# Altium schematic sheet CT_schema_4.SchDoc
size 187 x 159 mm
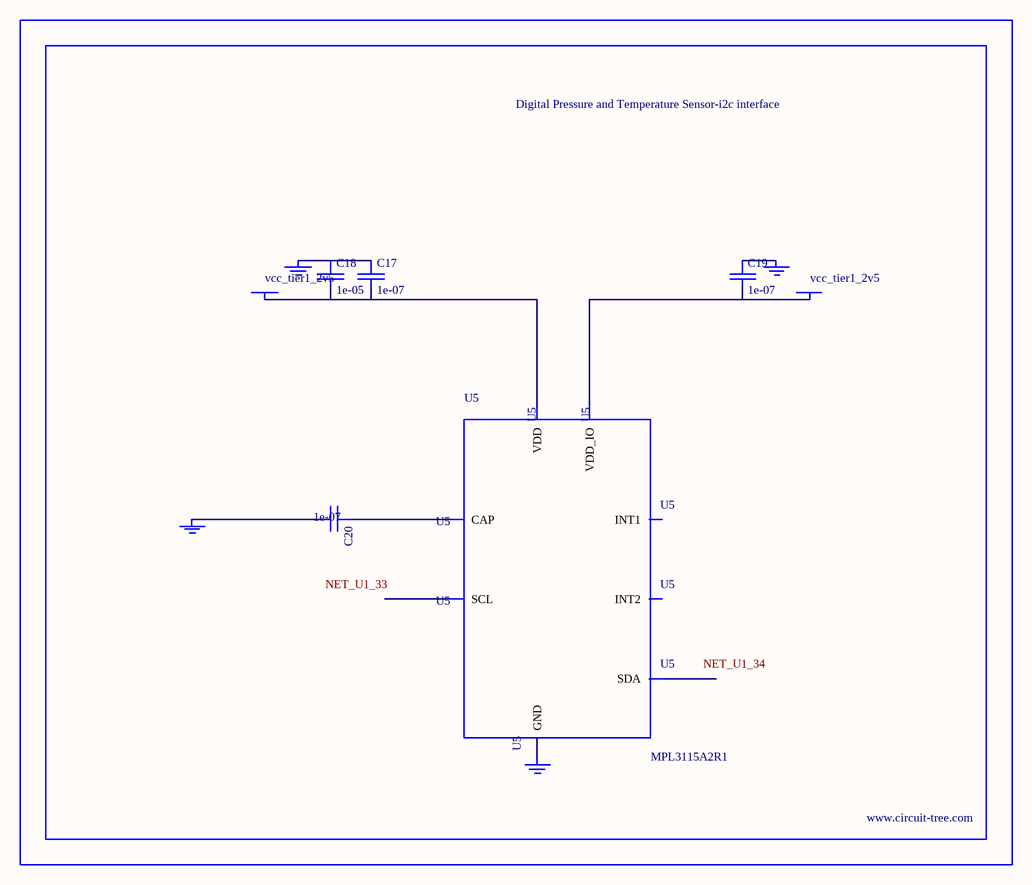
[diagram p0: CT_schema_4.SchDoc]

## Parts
BORDER3  (no value)
C17  1e-07  [C0402]
C18  1e-05  [C0805]
C19  1e-07  [C0402]
C20  1e-07  [C0402]
GND_INSTANCE_3_0  (no value)
GND_INSTANCE_3_1  (no value)
GND_INSTANCE_3_2  (no value)
GND_INSTANCE_3_3  (no value)
POWER_INSTANCE_3_0  vcc_tier1_2v5
POWER_INSTANCE_3_1  vcc_tier1_2v5
U5  MPL3115A2R1  [LGA-8]

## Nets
NetC17_1: C17.1 C18.1 GND_INSTANCE_3_0.0(GND)
NetC17_2: C17.2 C18.2 POWER_INSTANCE_3_0.0(PWR) U5.1(VDD)
NetC19_1: C19.1 GND_INSTANCE_3_2.0(GND)
NetC19_2: C19.2 POWER_INSTANCE_3_1.0(PWR) U5.4(VDD_IO)
NetC20_1: C20.1 U5.2(CAP)
NetC20_2: C20.2 GND_INSTANCE_3_1.0(GND)
NetGND_INSTANCE_3_3_0: GND_INSTANCE_3_3.0(GND) U5.3(GND)

Not connected (* = marked no-connect by the designer): U5 5(INT2) 6(INT1) 7(SDA) 8(SCL)

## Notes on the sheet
- Labels drawn without touching a wire or pin: NET_U1_33, NET_U1_34

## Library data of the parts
BORDER3 = BORDER_PAGE3
C17 C19 C20 = C0402C104K3RACTU
C18 = C0805C106K8RACTU
GND_INSTANCE_3_0-GND_INSTANCE_3_3 = GND
POWER_INSTANCE_3_0 POWER_INSTANCE_3_1 = PWR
